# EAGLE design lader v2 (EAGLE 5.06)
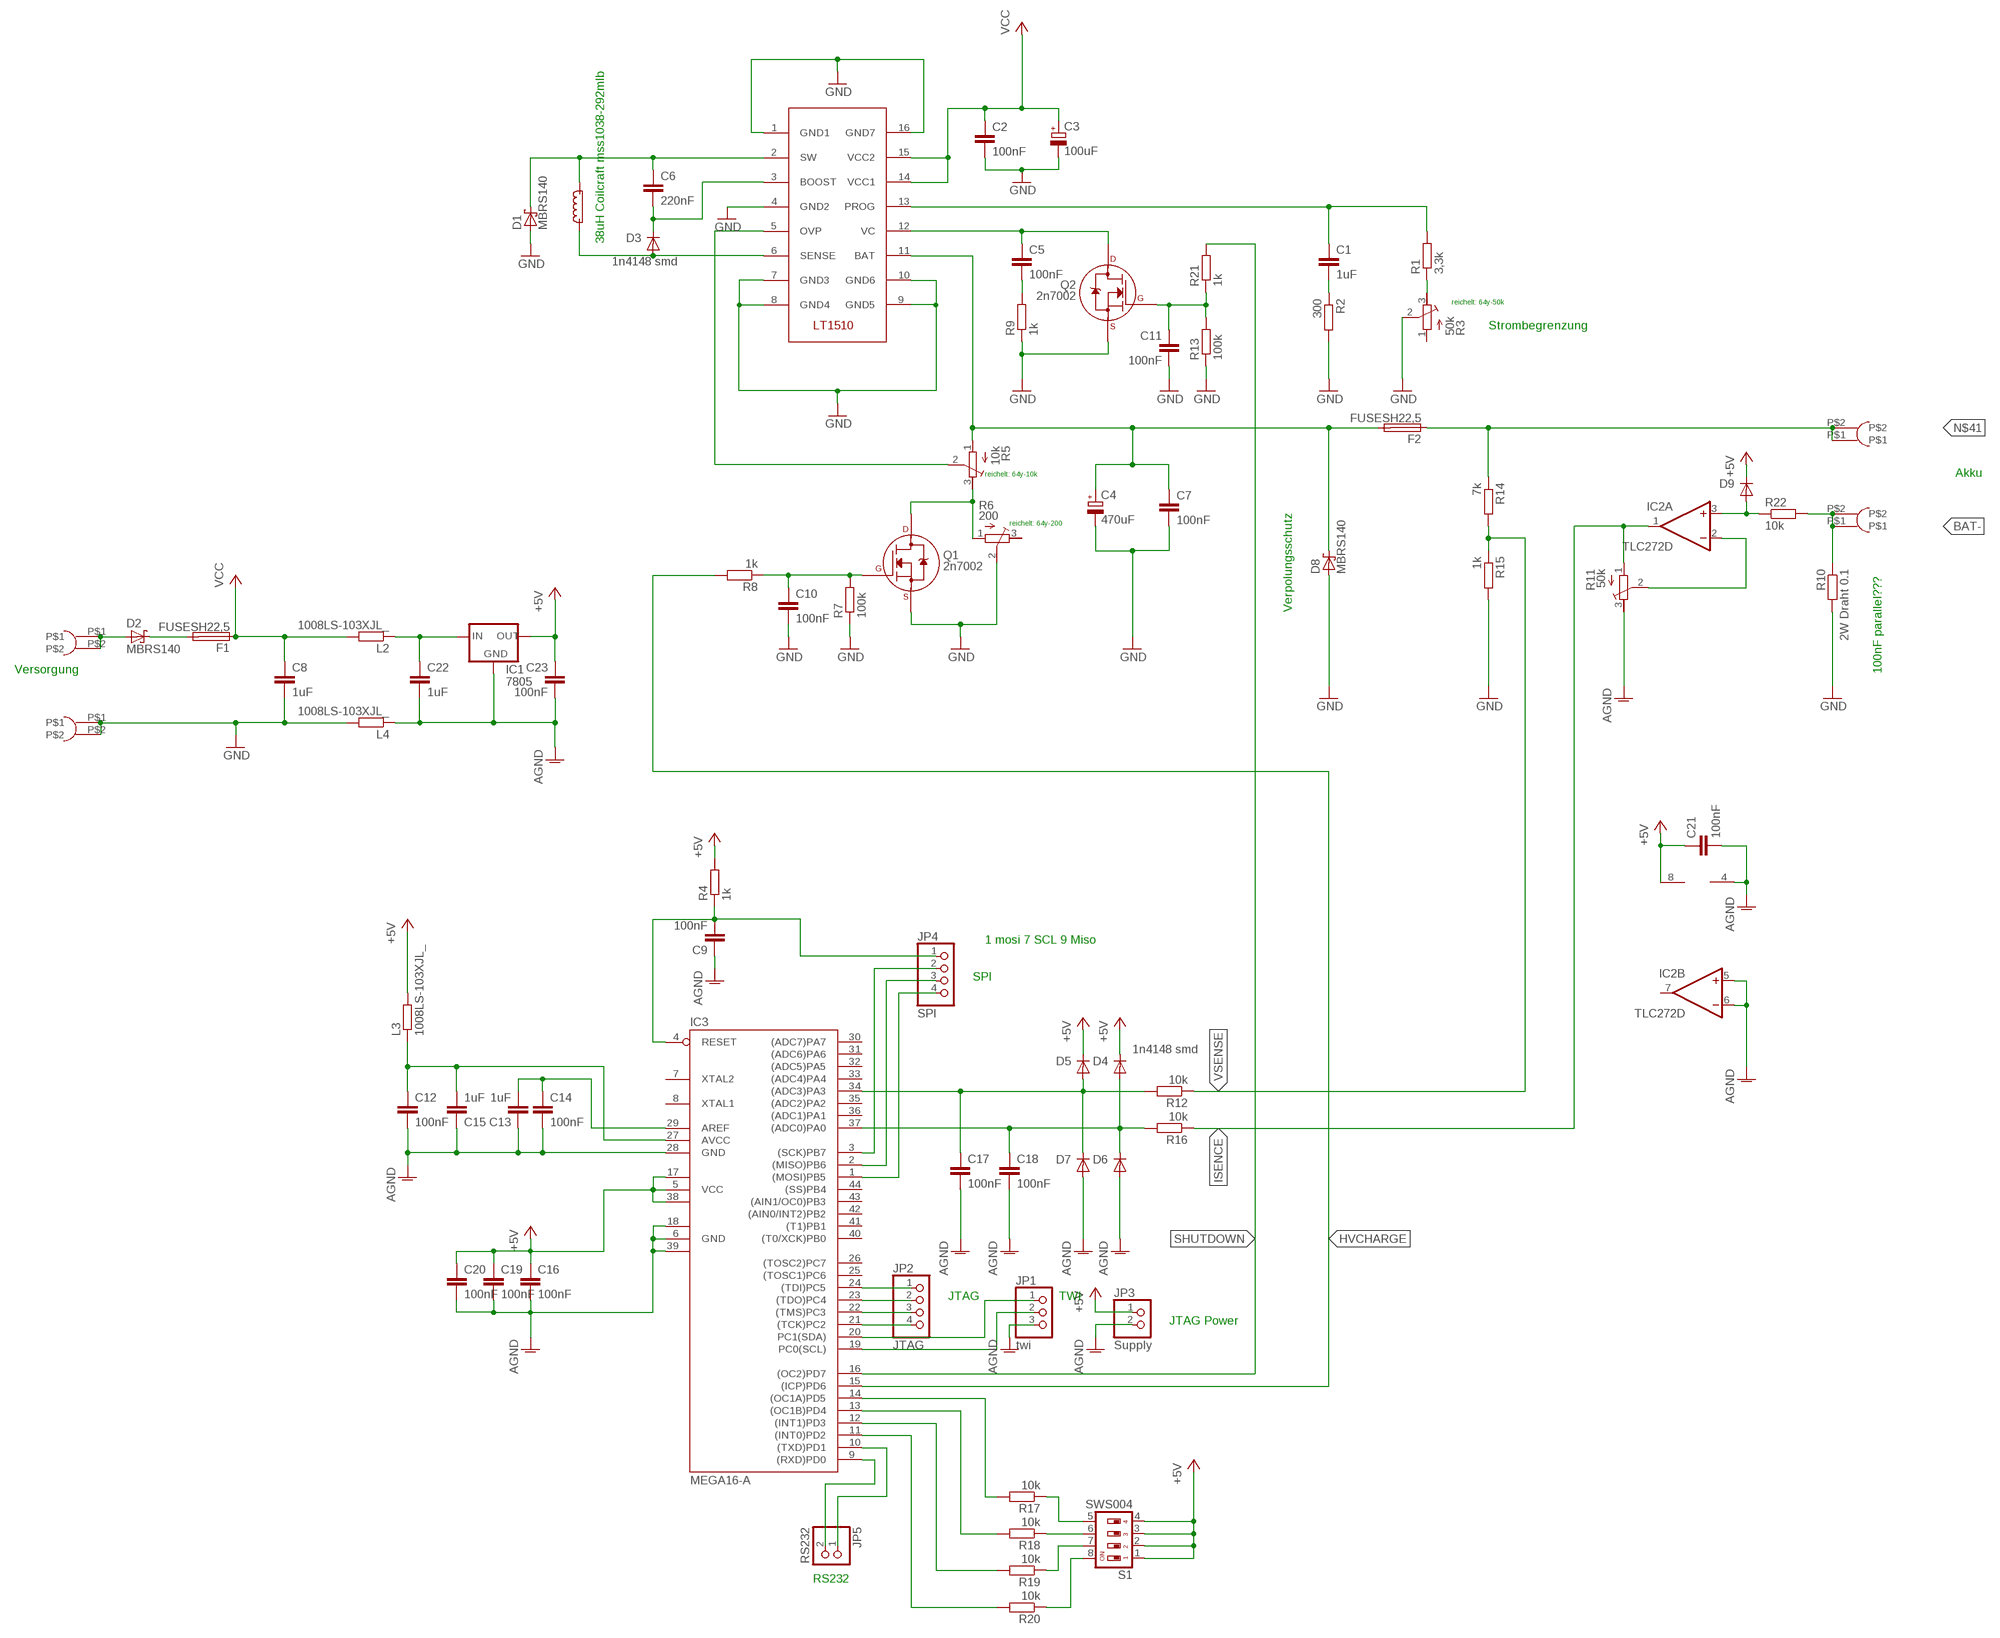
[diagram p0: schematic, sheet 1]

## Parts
C1  1uF  C-EUC3225  [C3225]
C2  100nF  C-EUC1206K  [C1206K]
C3  100uF  CPOL-EUD  [PANASONIC_D]
C4  470uF  CPOL-EUG  [PANASONIC_G]
C5  100nF  C-EUC1206K  [C1206K]
C6  220nF  C-EUC2220K  [C2220K]
C7  100nF  C-EUC1206K  [C1206K]
C8  1uF  C-EUC3225  [C3225]
C9  100nF  C-EUC1206K  [C1206K]
C10  100nF  C-EUC1206K  [C1206K]
C11  100nF  C-EUC1206K  [C1206K]
C12  100nF  C-EUC1206K  [C1206K]
C13  1uF  C-EUC3225  [C3225]
C14  100nF  C-EUC1206K  [C1206K]
C15  1uF  C-EUC3225  [C3225]
C16  100nF  C-EUC1206K  [C1206K]
C17  100nF  C-EUC1206K  [C1206K]
C18  100nF  C-EUC1206K  [C1206K]
C19  100nF  C-EUC1206K  [C1206K]
C20  100nF  C-EUC1206K  [C1206K]
C21  100nF  C-EUC1206K  [C1206K]
C22  1uF  C-EUC3225  [C3225]
C23  100nF  C-EUC1206K  [C1206K]
D1  MBRS140  MBRS130LT3  [SMB]
D2  MBRS140  MBRS130LT3  [SMB]
D3  1n4148 smd  DIODE-SOD80C  [SOD80C]
D4  1n4148 smd  DIODE-SOD80C  [SOD80C]
D5  1n4148 smd  DIODE-SOD80C  [SOD80C]
D6  1n4148 smd  DIODE-SOD80C  [SOD80C]
D7  1n4148 smd  DIODE-SOD80C  [SOD80C]
D8  MBRS140  MBRS130LT3  [SMB]
D9  1n4148 smd  DIODE-SOD80C  [SOD80C]
F1  FUSESH22,5  [SH22,5]
F2  FUSESH22,5  [SH22,5]
IC1  7805  78XXS  [78XXS]
IC2  TLC272D  [SO08]
IC3  MEGA16-A  [TQFP44]
JP1  twi  PINHD-1X3  [1X03]
JP2  JTAG  PINHD-1X4  [1X04]
JP3  Supply  PINHD-1X2  [1X02]
JP4  SPI  PINHD-1X4  [1X04]
JP5  RS232  PINHD-1X2  [1X02]
L2  1008LS-103XJL_  R-EU_R2512  [R2512]
L3  1008LS-103XJL_  R-EU_R2512  [R2512]
L4  1008LS-103XJL_  R-EU_R2512  [R2512]
Q1  2n7002  2N7002_SOT23  [SOT-23]
Q2  2n7002  2N7002_SOT23  [SOT-23]
R1  3,3k  R-EU_R1206  [R1206]
R2  300  R-EU_R1206  [R1206]
R3  50k  R-TRIMM64Y  [RTRIM64Y]
R4  1k  R-EU_R1206  [R1206]
R5  10k  R-TRIMM64Y  [RTRIM64Y]
R6  200  R-TRIMM64Y  [RTRIM64Y]
R7  100k  R-EU_R1206  [R1206]
R8  1k  R-EU_R1206  [R1206]
R9  1k  R-EU_R1206  [R1206]
R10  2W Draht 0.1  R-EU_0617/5V  [0617V]
R11  50k  R-TRIMM64Y  [RTRIM64Y]
R12  10k  R-EU_R1206  [R1206]
R13  100k  R-EU_R1206  [R1206]
R14  7k  R-EU_R1206  [R1206]
R15  1k  R-EU_R1206  [R1206]
R16  10k  R-EU_R1206  [R1206]
R17  10k  R-EU_R1206  [R1206]
R18  10k  R-EU_R1206  [R1206]
R19  10k  R-EU_R1206  [R1206]
R20  10k  R-EU_R1206  [R1206]
R21  1k  R-EU_R1206  [R1206]
R22  10k  R-EU_R1206  [R1206]
S1  SWS004  [SMS-004]
U$1  LT1510  [SO16]
U$2  39uH  COILCRAFTÄ-MSS1038  [COILCRAFT-MSS1038]
U$3  CON-FLACHSTECKER  [5MM-FLACHSTECKER]
U$4  CON-FLACHSTECKER  [5MM-FLACHSTECKER]
U$6  CON-FLACHSTECKER  [5MM-FLACHSTECKER]
U$7  CON-FLACHSTECKER  [5MM-FLACHSTECKER]

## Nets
+5V: C16.1 C19.1 C20.1 C21.1 C23.1 D4.C D5.C D9.C IC1.OUT IC2.8(P:V+) IC3.5(VCC) IC3.17(VCC1) IC3.38(VCC2) JP3.1 L3.2 R4.2 S1.1 S1.2 S1.3 S1.4
AGND: C9.1 C12.2 C13.1 C14.2 C15.1 C16.2 C17.2 C18.2 C19.2 C20.2 C21.2 C22.2 C23.2 D6.A D7.A IC1.GND IC2.4(P:V-) IC2.5(B:+IN) IC2.6(B:-IN) IC3.6(GND) IC3.18(GND1) IC3.28(GND) IC3.39(GND2) JP1.3 JP3.2 L4.1 R11.3(A)
BAT+: C4.+ C7.1 D8.C F2.2 R5.1(E) U$1.11(BAT)
BAT-: R10.1 R22.2 U$7.P$1 U$7.P$2
GND: C2.2 C3.- C4.- C7.2 C8.2 C10.2 C11.2 D1.A D8.A L4.2 Q1.2(S) Q2.2(S) R2.2 R3.2(S) R6.2(S) R7.1 R9.1 R10.2 R13.1 R15.2 U$1.1(GND1) U$1.4(GND2) U$1.7(GND3) U$1.8(GND4) U$1.9(GND5) U$1.10(GND6) U$1.16(GND7) U$4.P$1 U$4.P$2
HVCHARGE: IC3.15((ICP)PD6) R8.2
ISENCE: IC2.1(A:OUT) R11.1(E) R16.1
N$1: C5.1 Q2.3(D) U$1.12(VC)
N$2: C5.2 R9.2
N$3: C1.1 R1.2 U$1.13(PROG)
N$4: R1.1 R3.3(A)
N$5: C1.2 R2.1
N$6: IC2.2(A:-IN) R11.2(S)
N$7: C17.1 D5.A D7.C IC3.34((ADC3)PA3) R12.2
N$8: C11.1 Q2.1(G) R13.2 R21.1
N$9: C9.2 IC3.4(RESET) JP4.1 R4.1
N$10: C6.2 D3.C U$1.3(BOOST)
N$11: R5.2(S) U$1.5(OVP)
N$12: Q1.3(D) R5.3(A) R6.1(E)
N$13: C12.1 C15.2 IC3.27(AVCC) L3.1
N$14: C10.1 Q1.1(G) R7.2 R8.1
N$15: C13.2 C14.1 IC3.29(AREF)
N$16: C18.1 D4.A D6.C IC3.37((ADC0)PA0) R16.2
N$17: IC3.20(PC1(SDA)) JP1.1
N$18: IC3.19(PC0(SCL)) JP1.2
N$19: IC3.24((TDI)PC5) JP2.1
N$20: D9.A IC2.3(A:+IN) R22.1
N$21: IC3.3((SCK)PB7) JP4.2
N$22: IC3.11((INT0)PD2) R20.2
N$23: IC3.1((MOSI)PB5) JP4.4
N$24: IC3.23((TDO)PC4) JP2.2
N$25: IC3.2((MISO)PB6) JP4.3
N$26: IC3.22((TMS)PC3) JP2.3
N$27: IC3.21((TCK)PC2) JP2.4
N$29: D2.A U$3.P$1 U$3.P$2
N$30: D2.C F1.2
N$31: IC3.12((INT1)PD3) R19.2
N$32: IC3.13((OC1B)PD4) R18.2
N$33: C22.1 IC1.IN L2.1
N$34: IC3.14((OC1A)PD5) R17.2
N$35: IC3.9((RXD)PD0) JP5.2
N$36: IC3.10((TXD)PD1) JP5.1
N$37: R17.1 S1.5
N$38: R18.1 S1.6
N$39: R19.1 S1.7
N$40: R20.1 S1.8
N$41: F2.1 R14.1 U$6.P$1 U$6.P$2
SENCE: D3.A U$1.6(SENSE) U$2.P$1
SHUTDOWN: IC3.16((OC2)PD7) R21.2
SW: C6.1 D1.C U$1.2(SW) U$2.P$2
VCC: C2.1 C3.+ C8.1 F1.1 L2.2 U$1.14(VCC1) U$1.15(VCC2)
VSENSE: R12.1 R14.2 R15.1
Unconnected: IC2.7(B:OUT) IC3.7(XTAL2) IC3.8(XTAL1) IC3.25((TOSC1)PC6) IC3.26((TOSC2)PC7) IC3.30((ADC7)PA7) IC3.31((ADC6)PA6) IC3.32((ADC5)PA5) IC3.33((ADC4)PA4) IC3.35((ADC2)PA2) IC3.36((ADC1)PA1) IC3.40((T0/XCK)PB0) IC3.41((T1)PB1) IC3.42((AIN0/INT2)PB2) IC3.43((AIN1/OC0)PB3) IC3.44((SS)PB4) R3.1(E) R6.3(A)

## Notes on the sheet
- 38uH Coilcraft mss1038-292mlb
- reichelt: 64y-50k
- Strombegrenzung
- reichelt: 64y-10k | Akku
- reichelt: 64y-200
- Verpolungsschutz
- Versorgung | 100nF parallel???
- 1 mosi 7 SCL 9 Miso
- SPI
- JTAG | TWI
- JTAG Power
- RS232

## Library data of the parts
C1 C2 C5-C23 = rcl:C-EU: CAPACITOR, European symbol
C3 C4 = rcl:CPOL-EU: POLARIZED CAPACITOR, European symbol
D1 D2 D8 = diode:MBRS130LT3: Schottky Power Rectifier
D3-D7 D9 = diode:DIODE-: DIODE
F1 F2 = fuse:FUSE: Fuse
IC1 = v-reg:78XXS: VOLTAGE REGULATOR
IC2 = linear:TLC272: OP AMP
IC3 = atmel:MEGA16: MICROCONTROLLER 16 Kbytes FLASH 1 kbytes SRAM 512 bytes EEPROM USART 8-channel 10 bit ADC Source: avr.lbr
JP1 = pinhead:PINHD-1X3: PIN HEADER
JP2 JP4 = pinhead:PINHD-1X4: PIN HEADER
JP3 JP5 = pinhead:PINHD-1X2: PIN HEADER
L2-L4 R1 R2 R4 R7-R10 R12-R22 = rcl:R-EU_: RESISTOR, European symbol
Q1 Q2 = transistors-erweiterung:2N700*: 2N7000, 2N7002, NDS7002A N-channel enhancement mode MOSFET
R3 R5 R6 R11 = rcl:R-TRIMM: Trimm resistor
S1 = smd-special:SWS004: SMD Dip Switch 4 pol.
U$1 = lt1510:LT1510
U$2 = lt1510:COILCRAFTÄ-MSS1038
U$3 U$4 U$6 U$7 = rcld-neu:CON-FLACHSTECKER

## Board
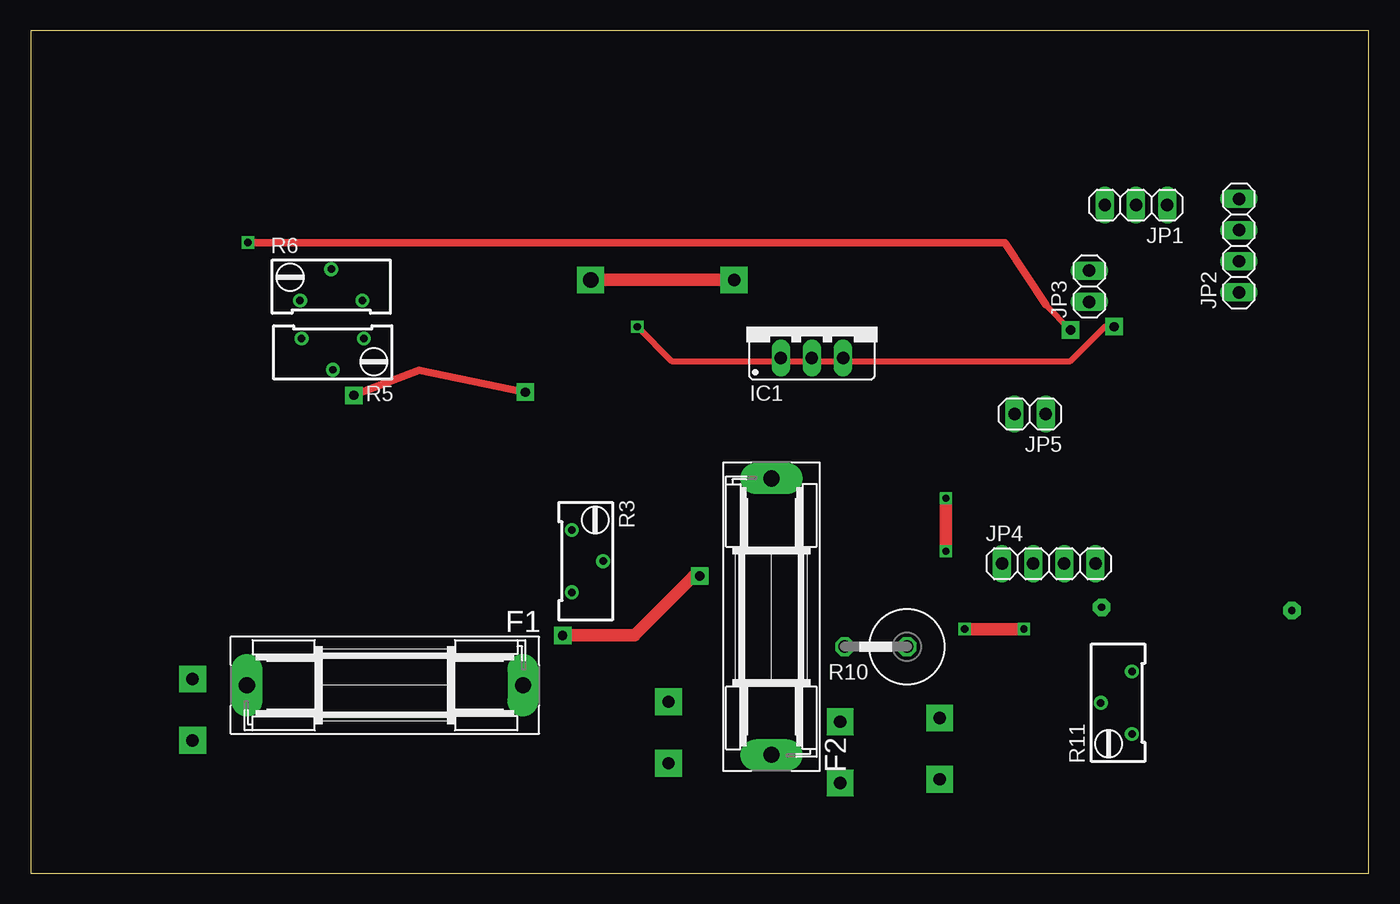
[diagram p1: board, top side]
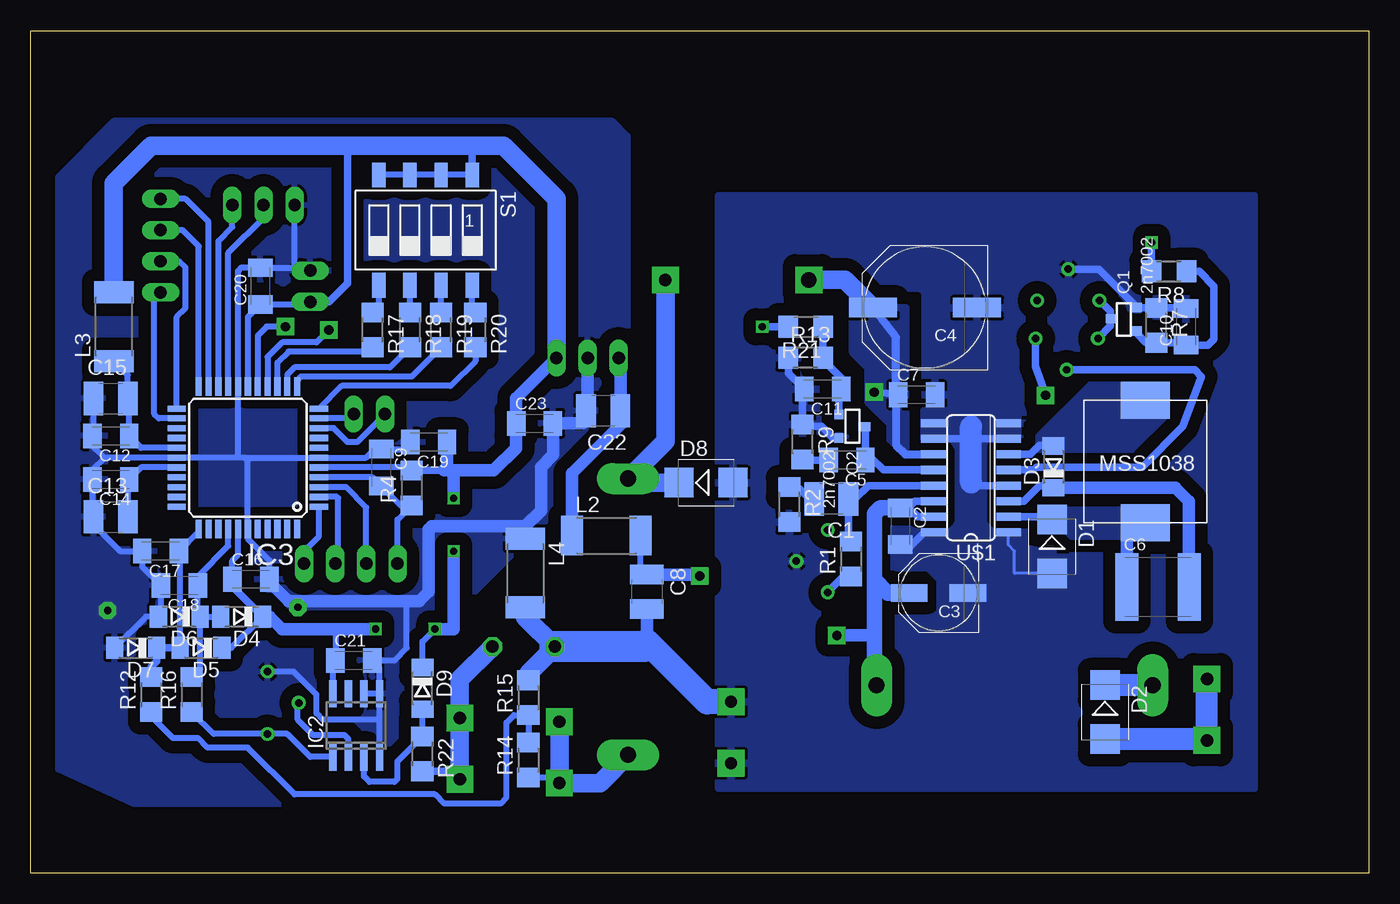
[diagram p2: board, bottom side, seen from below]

Size 109.06 x 68.65 mm. Coordinates in mm from the lower left corner, seen from the top.
Outline: 0,0 109.06,0 109.06,68.65 0,68.65 0,0
Copper layers (1*16): Top 0.035mm / dielectric 1.5mm / Bottom 0.035mm
Design rules "default *": minimum track width 20mil, minimum drill 24mil, track to track 25mil, track to pad 25mil, pad to pad 25mil, via to via 25mil, smd to smd 5mil, copper to edge 40mil, drill to drill 8mil, minimum pad ring 10mil, minimum via ring 8mil, stop-mask expansion 4mil, vias tented up to drill 0mil, thermal gap 10mil

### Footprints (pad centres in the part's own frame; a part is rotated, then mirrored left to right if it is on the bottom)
C3225 = smd 1.6 x 2.7: 1 -1.4,0; 2 1.4,0
C1206K = smd 1.5 x 2: 1 -1.5,0; 2 1.5,0
PANASONIC_D = smd 3 x 1.4: + 2.4,0; - -2.4,0
PANASONIC_G = smd 3.9 x 1.6: + 4.25,0; - -4.25,0
C2220K = smd 1.85 x 5.5: 1 -2.55,0; 2 2.55,0
SMB = smd 2.4 x 2.4: A 2.2,0; C -2.2,0
SOD80C = smd 1.4 x 1.8: A 1.7,0; C -1.7,0
SH22,5 = drill 1.321 pad 2.54 long: 1 -11.252,0; 2 11.252,0
78XXS = drill 1.016 long: GND 0,-2.54; IN -2.54,-2.54; OUT 2.54,-2.54
SO08 = smd 0.6 x 2.2: 1 -1.905,-2.6; 2 -0.635,-2.6; 3 0.635,-2.6; 4 1.905,-2.6; 5 1.905,2.6; 6 0.635,2.6; 7 -0.635,2.6; 8 -1.905,2.6
TQFP44 = smd 1.5 x 0.5: 1 -5.8,4; 2 -5.8,3.2; 3 -5.8,2.4; 4 -5.8,1.6; 5 -5.8,0.8; 6 -5.8,0; 7 -5.8,-0.8; 8 -5.8,-1.6; 9 -5.8,-2.4; 10 -5.8,-3.2; 11 -5.8,-4; 23 5.8,-4; 24 5.8,-3.2; 25 5.8,-2.4; 26 5.8,-1.6; 27 5.8,-0.8; 28 5.8,0; 29 5.8,0.8; 30 5.8,1.6; 31 5.8,2.4; 32 5.8,3.2; 33 5.8,4 | smd 0.5 x 1.5: 12 -4,-5.8; 13 -3.2,-5.8; 14 -2.4,-5.8; 15 -1.6,-5.8; 16 -0.8,-5.8; 17 0,-5.8; 18 0.8,-5.8; 19 1.6,-5.8; 20 2.4,-5.8; 21 3.2,-5.8; 22 4,-5.8; 34 4,5.8; 35 3.2,5.8; 36 2.4,5.8; 37 1.6,5.8; 38 0.8,5.8; 39 0,5.8; 40 -0.8,5.8; 41 -1.6,5.8; 42 -2.4,5.8; 43 -3.2,5.8; 44 -4,5.8
1X03 = drill 1.016 long: 1 -2.54,0; 2 0,0; 3 2.54,0
1X04 = drill 1.016 long: 1 -3.81,0; 2 -1.27,0; 3 1.27,0; 4 3.81,0
1X02 = drill 1.016 long: 1 -1.27,0; 2 1.27,0
R2512 = smd 1.8 x 3.2: 1 -2.8,0; 2 2.8,0
SOT-23 = smd 0.762 x 0.762: 1 -0.979,-1.101; 2 0.94,-1.101; 3 0.025,1.067
R1206 = smd 1.6 x 1.803: 1 -1.422,0; 2 1.422,0
RTRIM64Y = drill 0.61 round: 1 0,-2.54; 2 -2.54,0; 3 0,2.54
0617V = drill 1.016 octagon: 1 -2.54,0; 2 2.54,0
SMS-004 = smd 1.092 x 2.007: 1 -3.81,-4.496; 2 -1.27,-4.496; 3 1.27,-4.496; 4 3.81,-4.496; 5 3.81,4.496; 6 1.27,4.496; 7 -1.27,4.496; 8 -3.81,4.496
SO16 = smd 0.66 x 2.032: 1 -4.445,-3.073; 2 -3.175,-3.073; 3 -1.905,-3.073; 4 -0.635,-3.073; 5 0.635,-3.073; 6 1.905,-3.073; 7 3.175,-3.073; 8 4.445,-3.073; 9 4.445,3.073; 10 3.175,3.073; 11 1.905,3.073; 12 0.635,3.073; 13 -0.635,3.073; 14 -1.905,3.073; 15 -3.175,3.073; 16 -4.445,3.073
COILCRAFT-MSS1038 = smd 4 x 3: P$1 0,-1.5; P$2 0,8.5
5MM-FLACHSTECKER = drill 1 pad 2.184 square: P$1 0,0; P$2 5,0

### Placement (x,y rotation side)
C1  43.81,30.5 180 bottom
C2  38.18,28.27 270 bottom
C3  35.06,22.83 180 bottom
C4  36.18,46.08 180 bottom
C5  42.53,33.66 180 bottom
C6  17.18,23.32 0 bottom
C7  36.86,38.99 0 bottom
C8  58.85,22.94 270 bottom
C9  80.49,33.05 270 bottom
C10  14.91,44.53 90 bottom
C11  44.52,39.45 180 bottom
C12  102.54,35.64 180 bottom
C13  102.54,29.03 0 bottom
C14  102.54,32.08 180 bottom
C15  102.54,38.69 0 bottom
C16  91.11,23.95 0 bottom
C17  98.47,26.24 180 bottom
C18  96.95,23.45 180 bottom
C19  76.63,35.13 180 bottom
C20  90.34,47.83 90 bottom
C21  82.72,17.35 0 bottom
C22  62.4,37.67 180 bottom
C23  67.99,36.65 0 bottom
D1  25.83,26.63 270 bottom
D2  21.51,13.12 270 bottom
D3  25.7,33.11 90 bottom
D4  91.87,20.91 180 bottom
D5  95.17,18.37 180 bottom
D6  96.95,20.91 180 bottom
D7  100.5,18.37 180 bottom
D8  54.02,31.83 0 bottom
D9  77.14,15.06 270 bottom
F1  28.88,15.32 180 top
F2  60.37,20.91 90 top
IC1  63.67,44.53 0 top
IC2  82.53,12.03 0 bottom
IC3  91.36,33.86 180 bottom
JP1  90.09,54.43 180 top
JP2  98.47,51.13 90 top
JP3  86.28,47.83 90 top
JP4  82.98,25.22 0 top
JP5  81.45,37.42 180 top
L2  62.15,27.51 0 bottom
L3  102.28,44.53 90 bottom
L4  68.75,24.46 270 bottom
Q1  19.99,45.15 90 bottom
Q2  42.08,36.4 270 bottom
R1  42.2,25.6 90 bottom
R2  47.23,30.04 270 bottom
R3  44.11,25.43 180 top
R4  78.01,31.4 90 bottom
R5  24.62,43.56 90 top
R6  24.5,46.67 270 top
R7  17.32,44.64 270 bottom
R8  16.29,49.03 180 bottom
R9  46.15,35.14 270 bottom
R10  68.88,18.46 180 top
R11  89.76,13.89 0 top
R12  99.23,14.56 90 bottom
R13  45.89,41.99 0 bottom
R14  68.5,9.22 90 bottom
R15  68.5,14.3 90 bottom
R16  95.93,14.56 90 bottom
R17  81.2,44.27 270 bottom
R18  78.15,44.27 270 bottom
R19  75.61,44.27 270 bottom
R20  72.82,44.27 270 bottom
R21  45.89,44.53 180 bottom
R22  77.14,9.73 270 bottom
S1  76.88,52.4 180 bottom
U$1  32.43,32.22 90 bottom
U$2  18.21,37.05 180 bottom
U$3  13.19,15.82 270 top
U$4  51.98,8.97 90 top
U$6  65.98,12.35 270 top
U$7  74.09,12.65 270 top

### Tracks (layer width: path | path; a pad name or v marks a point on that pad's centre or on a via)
+5V  (via drill 0.6)
  Top 1.016: v74.6,26.24 v74.6,30.56 | v76.12,19.89 v80.95,19.89
  Bottom 0.483: IC3.17 91.36,45.31 C20.1 86.51,46.33 JP3.1 | IC3.38 92.16,25.95 92.63,25.48 92.63,23.98 C16.1 | 78.25,33.06 IC3.5 | 92.71,18.37 D5.C | 80.77,56.97 S1.4 S1.3 S1.2 S1.1
  Bottom 0.508: D4.C 92.71,18.37 | IC2.8 84.44,17.13 C21.1 84.22,19.61 84.5,19.89 | D9.C 77.14,18.87 v76.12,19.89
  Bottom 0.61: C16.1 92.61,23.34 D4.C | 73.07,59.26 S1.1 | JP3.1 84.76,46.56 83.23,48.08 83.23,59.26 | 74.6,32.82 R4.2 77.41,32.82 77.39,32.84 78.03,32.84 78.25,33.06
  Bottom 1.016: v74.6,26.24 74.6,19.89 v76.12,19.89 | 74.85,32.82 74.6,32.82 71.32,32.82 69.52,34.62 69.52,36.63 C23.1 69.49,38.71 IC1.OUT | 74.85,32.82 75.36,32.82 75.13,33.05 C19.1 | v74.6,30.56 74.6,32.57 74.85,32.82 | D4.C 89.58,20.91 88.57,19.89 84.5,19.89 v80.95,19.89
  Bottom 1.524: L3.2 102.28,56.21 99.23,59.26 83.23,59.26 73.07,59.26 70.53,59.26 66.21,54.94 IC1.OUT
AGND  (via drill 0.6 pad 1.42)
  Bottom 0.483: IC3.28 103.04,33.86 | 103.04,33.86 104.31,35.13 104.31,35.36 C12.2 103.94,35.74 C15.1 | 103.04,33.86 104.04,32.87 C14.2 104.04,29.13 C13.1 103.94,28.4 101.77,26.24 C17.2 99.97,24.97 C18.2 98.45,21.11 D6.A 99.66,20.91 D7.A | IC3.18 92.16,49.06 91.87,49.35 90.37,49.35 C20.2 87.55,49.33 | IC3.39 91.36,27.26 89.58,25.48 89.58,23.98 C16.2 | 87.55,49.33 86.51,49.33 JP3.2 | 87.55,49.33 JP1.3 | IC3.6 81.71,33.86 81.2,34.37 80.67,34.37 C9.1 78.71,34.55 C19.2 | 64.06,36.65 C22.2
  Bottom 0.508: 91.61,33.86 IC3.6 | 91.61,33.86 92.38,33.86 | 92.38,33.86 IC3.28 | IC3.18 92.16,34.08 92.38,33.86 | IC3.39 91.36,33.61 91.61,33.86 | IC2.4 80.63,12.52 | 80.63,12.52 IC2.5 | IC2.5 IC2.6 | IC2.5 80.63,16.75 C21.2 79.42,17.35 78.41,18.37 78.41,22.18 | R11.3 87.64,16.43 85.77,14.56 85.77,13.03 85.26,12.52 80.63,12.52 | v87.3,21.67 87.55,21.67 88.06,22.18
  Bottom 1.016: 68.75,28.27 67.48,29.54 67.48,33.1 66.47,34.11 66.47,36.63 C23.2 64.06,36.65 | 68.75,28.27 L4.1 | C16.2 89.58,23.95 89.58,23.7 88.06,22.18 78.41,22.18 77.39,22.18 76.63,22.94 76.63,28.02 76.37,28.27 68.75,28.27 | IC1.GND 63.67,37.8 C22.2
  other vias: 102.79,21.41
  pour Bottom (isolate 1.016): 61.64,61.29 102.28,61.29 106.85,56.72 106.85,8.46 100.76,5.67 74.09,5.67 74.09,21.67 60.37,35.38 60.37,60.02
BAT+  (via drill 0.76 pad 1.42, 1.02 pad 2.18, 1.27 pad 2.18)
  Top 0.61: v26.34,38.94 31.67,40.97 v40.31,39.19
  Top 1.016: v45.64,48.34 v57.32,48.34
  Bottom 0.61: v40.31,39.19 40.26,39.24 C7.1 | R5.1 27.16,41.29 v26.34,38.94
  Bottom 0.66: U$1.11 37.78,34.13 38.53,34.88 38.53,38.94 | 38.53,38.94 38.53,43.67 C4.+ | C7.1 38.48,38.99 38.53,38.94
  Bottom 1.016: 45.42,48.37 v45.64,48.34
  Bottom 1.524: v57.32,48.34 57.32,35.21 F2.2 60.04,31.83 D8.C | 45.42,48.37 42.72,48.37 C4.+
  pour Bottom: 37.77,34.37 37.77,46.05 42.08,46.05 42.08,45.04 42.08,42.5 40.81,41.23 40.81,38.43 39.04,36.65 39.04,35.38 38.02,34.37
BAT-
  Bottom 0.61: R22.2 74.74,8.31 U$7.P$2
  Bottom 1.524: U$7.P$2 U$7.P$1 74.09,15.79 R10.1
GND
  Bottom 0.254: D1.A 28.85,24.43 28.88,24.46 28.88,26.24 29.38,26.75 29.38,27.76
  Bottom 0.406: 32.69,35.38 32.69,35.4 | 35.5,35.38 U$1.10
  Bottom 0.508: 68.5,16.3 R15.2
  Bottom 0.61: 35.5,35.38 32.69,35.38 32.67,35.4 U$1.7 | U$1.16 36.23,27.78 37.51,26.49 37.9,26.49 C2.2 | Q2.2 43.68,35.46 44.62,36.4 45.98,36.4 R9.1 46.15,39.32 C11.2 47.32,40.75 R13.1 | U$1.4 31.94,31.59 32.18,31.83 32.43,31.83 | 32.43,36.4 32.18,36.65 | C10.2 14.94,46.06 R7.1 18.86,46.06 Q1.2 22.01,49.21 R6.2
  Bottom 1.016: C8.2 58.85,18.87 58.85,18.62 59.01,18.46 | 68.75,20.87 L4.2 68.9,21.52
  Bottom 1.524: 68.75,20.87 R10.2 68.5,16.3
  Bottom 1.778: 32.43,31.83 32.43,36.4
  Bottom 2.032: U$4.P$2 53.94,13.97 58.85,18.87
  Bottom 2.54: 59.01,18.46 R10.2
  pour Bottom (isolate 0.635, no thermals): 31.42,28.53 30.91,28.02 28.11,28.02 28.11,26.75 27.1,25.73 24.56,25.73 24.56,20.14 34.46,20.14 34.97,20.65 34.97,23.95 35.99,24.97 39.04,24.97 39.04,28.02 33.96,28.02 33.45,28.53 33.45,34.62 33.96,35.38 36.24,35.38 36.24,37.67 28.62,37.67 28.62,35.38 31.16,35.38 31.42,34.88
  pour Bottom (isolate 1.016, rank 6): 9.32,6.94 9.32,55.2 53.01,55.2 53.01,6.94
HVCHARGE  (via drill 0.6, 0.76 pad 1.42)
  Top 0.508: 82.72,46.31 v84.76,44.27
  Top 0.61: v17.7,51.39 79.42,51.39 82.72,46.31
  Bottom 0.508: IC3.15 89.76,42.06 88.57,43.26 85.77,43.26 v84.76,44.27
  Bottom 0.61: R8.2 17.71,51.37 v17.7,51.39
ISENCE
  Bottom 0.508: R16.1 94.15,11.35 R11.1 88.15,11.35 86.28,9.48 84.48,9.48 IC2.1
N$1
  Bottom 0.61: U$1.12 39.56,32.86 40.56,33.86 40.83,33.86 C5.1 41.02,33.67 Q2.3
N$2
  Bottom 0.61: C5.2 46.08,33.66 R9.2
N$3
  Bottom 0.61: U$1.13 40.8,31.59 41.83,30.56 42.35,30.56 C1.1 42.41,27.24 R1.2
N$4
  Bottom 0.61: R1.1 42.82,24.18 R3.3
N$5
  Bottom 0.61: C1.2 45.58,30.5 46.4,31.32 47.09,31.32 R2.1
N$6
  Bottom 0.508: IC2.2 83.17,10.94 83.49,11.25 86.03,11.25 87.3,12.52 87.3,13.81 R11.2
N$7
  Bottom 0.483: IC3.34 95.36,27.85 C17.1
  Bottom 0.508: D5.A 96.87,26.14 C17.1
  Bottom 0.61: D5.A D7.C 98.8,17.27 99.23,16.84 R12.2
N$8
  Bottom 0.61: Q2.1 43.19,39.28 C11.1 42.85,39.62 42.85,40.21 44.47,41.84 R13.2 R21.1
N$9
  Bottom 0.483: IC3.4 81.19,32.26 C9.2
  Bottom 0.508: JP4.1 79.17,28.82 R4.1 78.91,29.98 C9.2
N$10
  Bottom 0.61: U$1.3 28.1,30.32 26.84,31.57 26.37,31.57 D3.C
  Bottom 1.016: D3.C 15.76,31.41 14.65,30.3 14.65,23.34 C6.2
N$11
  Bottom 0.61: U$1.5 27.34,32.86 27.1,33.1 18.46,33.1 15.16,36.4 13.64,40.46 14.19,41.02 R5.2
N$12
  Bottom 0.61: R6.1 21.05,45.77 Q1.3 21.05,44.59 R5.3
N$13
  Bottom 0.483: IC3.27 100.06,34.66 C12.1 101.04,38.59 C15.2 101.14,40.58 L3.1
N$14
  Bottom 0.61: Q1.1 18.89,43.94 18.21,43.26 17.36,43.26 R7.2 15.1,43.22 C10.1 14.88,43 13.13,43 12.62,43.51 12.62,47.83 13.82,49.03 R8.1
N$15
  Bottom 0.483: C13.2 101.14,31.98 C14.1 100.06,33.06 IC3.29
N$16
  Bottom 0.508: IC3.37 92.96,26.67 95.42,24.21 95.42,23.47 C18.1 95.45,21.11 D6.C | D6.C D4.A | D6.C 95.25,16.66 R16.2
N$17
  Bottom 0.483: IC3.20 93.76,51.53 92.63,52.66 JP1.1
N$18
  Bottom 0.483: IC3.19 92.96,50.55 90.09,53.42 JP1.2
N$19
  Bottom 0.483: IC3.24 98.62,37.06 98.98,37.42 98.98,46.81 JP2.1
N$20
  Bottom 0.508: IC2.3 81.9,7.89 81.45,7.44 79.42,7.44 79.17,7.7 79.17,9.12 R22.1 D9.A
N$21
  Bottom 0.508: IC3.3 83.37,31.46 81.71,29.8 JP4.2
N$22
  Bottom 0.483: IC3.11 83.72,39.7 74.85,39.7 72.82,41.73 R20.2
N$23
  Bottom 0.508: IC3.1 85.56,27.47 86.79,26.24 JP4.4
N$24
  Bottom 0.483: IC3.23 97.16,45.33 96.44,46.05 96.44,49.35 96.95,49.86 JP2.2
N$25
  Bottom 0.508: IC3.2 84.1,30.66 83.99,30.56 83.99,25.48 JP4.3
N$26
  Bottom 0.483: IC3.22 95.36,51.07 96.69,52.4 JP2.3
N$27
  Bottom 0.483: IC3.21 94.56,53.06 96.44,54.94 JP2.4
N$29
  Bottom 1.778: D2.A 13.29,10.92 U$3.P$2 U$3.P$1
N$30
  Bottom 1.778: D2.C F1.2
N$31
  Bottom 0.483: IC3.12 87.36,40.15 87.04,40.46 78,40.46 R19.2
N$32
  Bottom 0.483: IC3.13 88.16,40.62 87.55,41.23 79.78,41.23 R18.2
N$33
  Bottom 1.016: L2.1 64.95,32.58 60.88,36.65 60.88,37.55 C22.1 61,41.86 IC1.IN
N$34
  Bottom 0.483: IC3.14 88.96,41.59 88.06,42.5 81.56,42.5 R17.2
N$35
  Bottom 0.483: IC3.9 84.36,36.26 83.23,35.13 82.47,35.13 JP5.2
N$36
  Bottom 0.483: IC3.10 83.08,37.06 JP5.1
N$37
  Bottom 0.483: S1.5 80.69,46.2 R17.1
N$38
  Bottom 0.483: R18.1 S1.6
N$39
  Bottom 0.483: R19.1 S1.7
N$40
  Bottom 0.483: S1.8 73.07,45.95 R20.1
N$41
  Bottom 0.508: R14.1 66.43,7.8 U$6.P$2
  Bottom 1.524: U$6.P$1 U$6.P$2 62.67,7.35 F2.1
SENCE
  Bottom 0.61: U$1.6 27.59,34.13 26.84,34.88 26.27,34.88 D3.A
  pour Bottom (no thermals): 27.1,34.37 19.22,34.37 16.43,37.16 16.43,39.96 22.78,39.96 27.1,35.64
SHUTDOWN  (via drill 0.6, 0.76 pad 1.42)
  Top 0.508: v88.31,44.53 87.55,44.53 84.76,41.73 52.24,41.73 v49.45,44.53
  Bottom 0.508: IC3.16 90.56,43.8 89.84,44.53 v88.31,44.53
  Bottom 0.61: R21.2 v49.45,44.53
SW
  Bottom 0.61: U$1.2 26.04,29.05 D1.C
  Bottom 1.016: C6.1 19.73,27.77 18.72,28.78 18.44,28.78 U$2.P$2
  pour Bottom (no thermals): 26.84,29.8 16.43,29.8 16.43,27.26 24.3,27.26 24.81,27.76 26.84,27.76
VCC  (via drill 0.76 pad 1.42)
  Top 1.016: v54.53,24.21 54.02,24.21 49.2,19.38 v43.35,19.38
  Bottom 0.483: L2.2 59.35,24.84 C8.1
  Bottom 0.61: U$1.14 36.99,30.32 37.51,29.8 | 37.51,29.8 38.16,29.8 C2.1 | U$1.15 36.76,29.05 37.51,29.8
  Bottom 1.016: C8.1 54.66,24.34 v54.53,24.21 | 40.31,19.38 v43.35,19.38
  Bottom 1.27: C3.+ 39.18,22.83 40.31,23.95 | 40.31,23.95 40.31,29.29 39.8,29.8 38.2,29.8 C2.1 | 40.31,23.95 40.31,19.38 40.31,15.5 F1.1
VSENSE
  Bottom 0.508: R14.2 R15.1 69.67,12.88 70.28,12.27 70.28,6.17 70.79,5.67 75.36,5.67 76.12,6.43 87.55,6.43 91.36,10.24 94.66,10.24 95.42,11 97.46,11 99.23,12.78 R12.1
